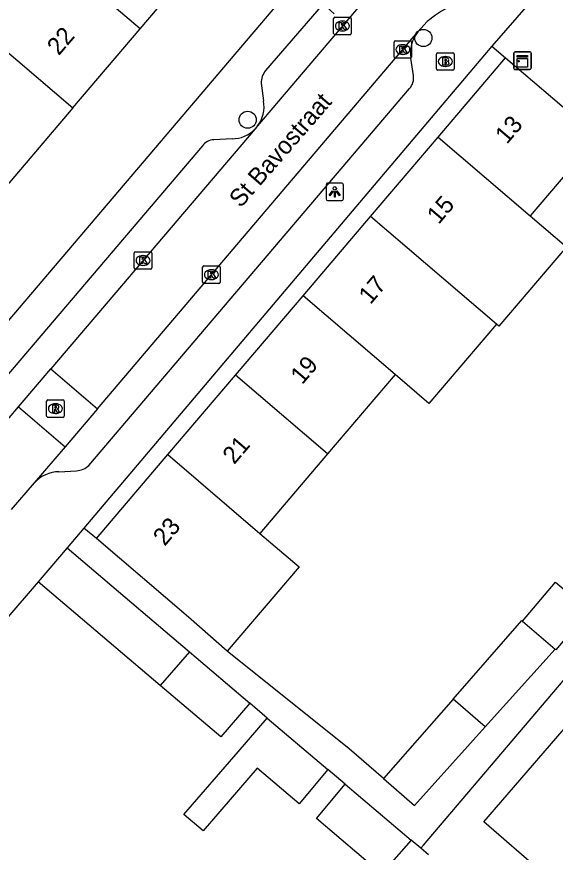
# Model space of a CAD drawing. Extents: x 162532 to 163264, y 381233 to 382042.
# Drawn here: x 163066.13 to 163096.93, y 381621.44 to 381669.17 of the extents above; entities that cross this region are included whole.
import ezdxf

# ---------------------------------------------------------------- set-up
doc = ezdxf.new("R2010")
doc.units = 0
for name, color, linetype in [('IMGEO_Boom', 7, 'Continuous'), ('IMGEO_Brandkraan', 7, 'Continuous'), ('IMGEO_Kast', 7, 'Continuous'), ('IMGEO_Kolk', 7, 'Continuous'), ('IMGEO_Lichtpunt', 7, 'Continuous'), ('IMGEO_Muur', 7, 'Continuous'), ('IMGEO_Openbare_ruimte_label', 7, 'Continuous'), ('IMGEO_Pand', 7, 'Continuous'), ('IMGEO_Pand_nummerreeks', 7, 'Continuous'), ('IMGEO_Rijbaan_lokaal_open', 7, 'Continuous'), ('IMGEO_Rioolput', 7, 'Continuous'), ('IMGEO_Voetpad_open', 7, 'Continuous')]:
    doc.layers.add(name, color=color, linetype=linetype)

msp = doc.modelspace()

# ---------------------------------------------------------------- linework, layer by layer
at = {"layer": 'IMGEO_Boom'}
for centre in [(163089.383, 381667.956), (163079.338, 381663.284)]:
    msp.add_circle(centre, 0.489, dxfattribs=at)
at = {"layer": 'IMGEO_Brandkraan'}
for p, q in [((163090.138, 381666.187), (163090.138, 381667.039)), ((163090.213, 381667.113), (163091.065, 381667.113)), ((163091.139, 381667.039), (163091.139, 381666.187)), ((163090.626, 381666.893), (163090.651, 381666.893)), ((163091.065, 381666.113), (163090.213, 381666.113)), ((163090.649, 381666.333), (163090.624, 381666.333))]:
    msp.add_line(p, q, dxfattribs=at)
for points in [[(163090.138, 381666.187), (163090.138, 381667.039)], [(163090.213, 381667.113), (163091.065, 381667.113)], [(163091.139, 381667.039), (163091.139, 381666.187)], [(163090.486, 381666.813), (163090.486, 381666.413), (163090.699, 381666.413)], [(163090.717, 381666.813), (163090.486, 381666.813)], [(163090.665, 381666.732), (163090.611, 381666.732), (163090.611, 381666.656)], [(163090.611, 381666.656), (163090.664, 381666.656)], [(163090.673, 381666.58), (163090.611, 381666.58), (163090.611, 381666.499)], [(163091.065, 381666.113), (163090.213, 381666.113)], [(163090.611, 381666.499), (163090.673, 381666.499)]]:
    msp.add_lwpolyline(points, dxfattribs=at)
for centre, radius, start, end in [((163090.215, 381667.037), 0.0765, 91.552, 178.448), ((163090.215, 381667.037), 0.0765, 91.552, 178.448), ((163091.063, 381667.037), 0.0765, 1.552, 88.448), ((163091.063, 381667.037), 0.0765, 1.552, 88.448), ((163090.666, 381666.694), 0.0379, 267.8285, 90.9355), ((163090.674, 381666.539), 0.0404, 269.8759, 90.5077), ((163090.721, 381666.668), 0.145, 59.4692, 91.5367), ((163090.746, 381666.715), 0.0922, 285.5137, 58.1501), ((163090.751, 381666.523), 0.105, 301.3115, 78.989), ((163090.215, 381666.189), 0.0765, 181.552, 268.448), ((163090.215, 381666.189), 0.0765, 181.552, 268.448), ((163090.705, 381666.664), 0.251, 268.6676, 293.5347), ((163091.063, 381666.189), 0.0765, 271.552, 358.448), ((163091.063, 381666.189), 0.0765, 271.552, 358.448)]:
    msp.add_arc(centre, radius, start, end, dxfattribs=at)
for centre, major_axis, ratio, start_param, end_param in [((163090.625, 381666.613), (-0.387, 0.002), 0.722429, 4.712389, 7.853982), ((163090.65, 381666.613), (-0.39, 0.002), 0.717154, 1.570796, 4.712389)]:
    msp.add_ellipse(centre, major_axis=major_axis, ratio=ratio, start_param=start_param, end_param=end_param, dxfattribs=at)
at = {"layer": 'IMGEO_Kast'}
for p, q in [((163094.549, 381666.235), (163094.549, 381667.076)), ((163094.549, 381667.076), (163094.549, 381666.235)), ((163094.624, 381667.16), (163095.465, 381667.16)), ((163095.465, 381667.16), (163094.624, 381667.16)), ((163095.549, 381667.085), (163095.549, 381666.244)), ((163095.549, 381666.244), (163095.549, 381667.085)), ((163095.474, 381666.16), (163094.633, 381666.16)), ((163094.633, 381666.16), (163095.474, 381666.16))]:
    msp.add_line(p, q, dxfattribs=at)
for points in [[(163094.744, 381666.95), (163095.344, 381666.95), (163095.344, 381666.865), (163094.744, 381666.865), (163094.744, 381666.95)], [(163094.744, 381666.775), (163095.344, 381666.775), (163095.344, 381666.286), (163094.744, 381666.286), (163094.744, 381666.775)]]:
    msp.add_lwpolyline(points, dxfattribs=at)
msp.add_circle((163094.828, 381666.624), 0.0377, dxfattribs=at)
for centre, start, end in [((163094.627, 381667.082), 92.4484, 184.2845), ((163094.627, 381667.082), 92.4484, 184.2845), ((163095.471, 381667.082), 2.4484, 94.2845), ((163095.471, 381667.082), 2.4484, 94.2845), ((163094.627, 381666.238), 182.4484, 274.2845), ((163094.627, 381666.238), 182.4484, 274.2845), ((163095.471, 381666.238), 272.4484, 4.2845), ((163095.471, 381666.238), 272.4484, 4.2845)]:
    msp.add_arc(centre, 0.0779, start, end, dxfattribs=at)
at = {"layer": 'IMGEO_Kolk'}
for p, q in [((163084.254, 381668.217), (163084.254, 381669.069)), ((163084.329, 381669.143), (163085.181, 381669.143)), ((163084.742, 381668.923), (163084.767, 381668.923)), ((163085.255, 381669.069), (163085.255, 381668.217)), ((163085.181, 381668.143), (163084.329, 381668.143)), ((163084.765, 381668.363), (163084.74, 381668.363)), ((163087.712, 381666.868), (163087.712, 381667.72)), ((163087.787, 381667.794), (163088.639, 381667.794)), ((163088.2, 381667.574), (163088.225, 381667.574)), ((163088.713, 381667.72), (163088.713, 381666.868)), ((163088.223, 381667.014), (163088.198, 381667.014)), ((163088.639, 381666.794), (163087.787, 381666.794)), ((163072.855, 381654.821), (163072.855, 381655.673)), ((163072.93, 381655.747), (163073.782, 381655.747)), ((163073.856, 381655.673), (163073.856, 381654.821)), ((163073.343, 381655.527), (163073.368, 381655.527)), ((163073.782, 381654.747), (163072.93, 381654.747)), ((163073.366, 381654.967), (163073.341, 381654.967)), ((163076.765, 381654.009), (163076.765, 381654.861)), ((163076.84, 381654.935), (163077.692, 381654.935)), ((163077.253, 381654.715), (163077.278, 381654.715)), ((163077.766, 381654.861), (163077.766, 381654.009)), ((163077.276, 381654.155), (163077.251, 381654.155)), ((163077.692, 381653.935), (163076.84, 381653.935))]:
    msp.add_line(p, q, dxfattribs=at)
for points in [[(163084.254, 381668.217), (163084.254, 381669.069)], [(163084.329, 381669.143), (163085.181, 381669.143)], [(163085.255, 381669.069), (163085.255, 381668.217)], [(163084.575, 381668.843), (163084.698, 381668.843), (163084.698, 381668.692), (163084.828, 381668.843), (163084.992, 381668.843), (163084.846, 381668.692), (163084.999, 381668.443), (163084.847, 381668.443), (163084.762, 381668.607), (163084.698, 381668.54), (163084.698, 381668.443), (163084.575, 381668.443), (163084.575, 381668.843)], [(163085.181, 381668.143), (163084.329, 381668.143)], [(163087.712, 381666.868), (163087.712, 381667.72)], [(163087.787, 381667.794), (163088.639, 381667.794)], [(163088.033, 381667.494), (163088.156, 381667.494), (163088.156, 381667.343), (163088.286, 381667.494), (163088.45, 381667.494), (163088.304, 381667.343), (163088.457, 381667.094), (163088.305, 381667.094), (163088.22, 381667.258), (163088.156, 381667.191), (163088.156, 381667.094), (163088.033, 381667.094), (163088.033, 381667.494)], [(163088.713, 381667.72), (163088.713, 381666.868)], [(163088.639, 381666.794), (163087.787, 381666.794)], [(163072.855, 381654.821), (163072.855, 381655.673)], [(163072.93, 381655.747), (163073.782, 381655.747)], [(163073.856, 381655.673), (163073.856, 381654.821)], [(163073.176, 381655.447), (163073.299, 381655.447), (163073.299, 381655.296), (163073.429, 381655.447), (163073.593, 381655.447), (163073.447, 381655.296), (163073.6, 381655.047), (163073.448, 381655.047), (163073.363, 381655.211), (163073.299, 381655.144), (163073.299, 381655.047), (163073.176, 381655.047), (163073.176, 381655.447)], [(163073.782, 381654.747), (163072.93, 381654.747)], [(163076.765, 381654.009), (163076.765, 381654.861)], [(163076.84, 381654.935), (163077.692, 381654.935)], [(163077.086, 381654.635), (163077.209, 381654.635), (163077.209, 381654.484), (163077.339, 381654.635), (163077.503, 381654.635), (163077.357, 381654.484), (163077.51, 381654.235), (163077.358, 381654.235), (163077.273, 381654.399), (163077.209, 381654.332), (163077.209, 381654.235), (163077.086, 381654.235), (163077.086, 381654.635)], [(163077.766, 381654.861), (163077.766, 381654.009)], [(163077.692, 381653.935), (163076.84, 381653.935)]]:
    msp.add_lwpolyline(points, dxfattribs=at)
for centre, start, end in [((163084.331, 381669.067), 91.552, 178.448), ((163084.331, 381669.067), 91.552, 178.448), ((163085.179, 381669.067), 1.552, 88.448), ((163085.179, 381669.067), 1.552, 88.448), ((163084.331, 381668.219), 181.552, 268.448), ((163084.331, 381668.219), 181.552, 268.448), ((163085.179, 381668.219), 271.552, 358.448), ((163085.179, 381668.219), 271.552, 358.448), ((163087.789, 381667.718), 91.552, 178.448), ((163087.789, 381667.718), 91.552, 178.448), ((163088.637, 381667.718), 1.552, 88.448), ((163088.637, 381667.718), 1.552, 88.448), ((163087.789, 381666.87), 181.552, 268.448), ((163087.789, 381666.87), 181.552, 268.448), ((163088.637, 381666.87), 271.552, 358.448), ((163088.637, 381666.87), 271.552, 358.448), ((163072.932, 381655.671), 91.552, 178.448), ((163072.932, 381655.671), 91.552, 178.448), ((163073.78, 381655.671), 1.552, 88.448), ((163073.78, 381655.671), 1.552, 88.448), ((163072.932, 381654.823), 181.552, 268.448), ((163072.932, 381654.823), 181.552, 268.448), ((163073.78, 381654.823), 271.552, 358.448), ((163073.78, 381654.823), 271.552, 358.448), ((163076.842, 381654.859), 91.552, 178.448), ((163076.842, 381654.859), 91.552, 178.448), ((163077.69, 381654.859), 1.552, 88.448), ((163077.69, 381654.859), 1.552, 88.448), ((163076.842, 381654.011), 181.552, 268.448), ((163076.842, 381654.011), 181.552, 268.448), ((163077.69, 381654.011), 271.552, 358.448), ((163077.69, 381654.011), 271.552, 358.448)]:
    msp.add_arc(centre, 0.0765, start, end, dxfattribs=at)
for centre, major_axis, ratio, start_param, end_param in [((163084.741, 381668.643), (-0.387, 0.002), 0.722429, 4.712389, 7.853982), ((163084.766, 381668.643), (-0.39, 0.002), 0.717154, 1.570796, 4.712389), ((163088.199, 381667.294), (-0.387, 0.002), 0.722429, 4.712389, 7.853982), ((163088.224, 381667.294), (-0.39, 0.002), 0.717154, 1.570796, 4.712389), ((163073.342, 381655.247), (-0.387, 0.002), 0.722429, 4.712389, 7.853982), ((163073.367, 381655.247), (-0.39, 0.002), 0.717154, 1.570796, 4.712389), ((163077.252, 381654.435), (-0.387, 0.002), 0.722429, 4.712389, 7.853982), ((163077.277, 381654.435), (-0.39, 0.002), 0.717154, 1.570796, 4.712389)]:
    msp.add_ellipse(centre, major_axis=major_axis, ratio=ratio, start_param=start_param, end_param=end_param, dxfattribs=at)
at = {"layer": 'IMGEO_Lichtpunt'}
for p, q in [((163083.818, 381659.567), (163083.818, 381658.76)), ((163083.818, 381659.567), (163083.818, 381658.76)), ((163084.72, 381659.662), (163083.912, 381659.662)), ((163084.72, 381659.662), (163083.912, 381659.662)), ((163084.814, 381658.76), (163084.814, 381659.567)), ((163084.814, 381658.76), (163084.814, 381659.567)), ((163083.912, 381658.666), (163084.72, 381658.666)), ((163083.912, 381658.666), (163084.72, 381658.666))]:
    msp.add_line(p, q, dxfattribs=at)
for points in [[(163084.192, 381659.231), (163084.231, 381659.203), (163084.043, 381658.941), (163084.005, 381658.968), (163084.192, 381659.231)], [(163084.294, 381659.183), (163084.341, 381659.183), (163084.341, 381658.861), (163084.294, 381658.861), (163084.294, 381659.183)], [(163084.404, 381659.203), (163084.442, 381659.23), (163084.629, 381658.968), (163084.59, 381658.94), (163084.404, 381659.203)]]:
    msp.add_lwpolyline(points, dxfattribs=at)
msp.add_circle((163084.317, 381659.365), 0.0994, dxfattribs=at)
for centre, start, end in [((163083.912, 381659.567), 90, 180), ((163083.912, 381659.567), 90, 180), ((163084.72, 381659.567), 0, 90), ((163084.72, 381659.567), 0, 90), ((163083.912, 381658.76), 180, 270), ((163083.912, 381658.76), 180, 270), ((163084.72, 381658.76), 270, 0), ((163084.72, 381658.76), 270, 360)]:
    msp.add_arc(centre, 0.0946, start, end, dxfattribs=at)
at = {"layer": 'IMGEO_Muur'}
msp.add_lwpolyline([(163067.361, 381636.896), (163065.516, 381634.738)], dxfattribs=at)
at = {"layer": 'IMGEO_Pand'}
for points in [[(163073.19, 381668.483), (163067.94, 381672.961), (163067.641, 381672.609)], [(163073.19, 381668.483), (163077.04, 381673.007)], [(163064.09, 381668.438), (163069.34, 381663.96)], [(163069.34, 381663.96), (163073.19, 381668.483)], [(163090.233, 381662.298), (163094.086, 381666.82)], [(163094.086, 381666.82), (163099.354, 381662.333)], [(163069.34, 381663.96), (163065.49, 381659.437)], [(163086.368, 381657.761), (163090.233, 381662.298)], [(163090.233, 381662.298), (163095.492, 381657.8)], [(163099.354, 381662.333), (163095.492, 381657.8)], [(163082.504, 381653.225), (163086.368, 381657.761)], [(163093.562, 381651.609), (163086.368, 381657.761)], [(163095.492, 381657.8), (163097.57, 381656.029), (163093.705, 381651.493), (163093.562, 381651.609)], [(163078.638, 381648.688), (163082.504, 381653.225)], [(163087.762, 381648.728), (163082.504, 381653.225)], [(163093.562, 381651.609), (163089.698, 381647.073), (163087.762, 381648.728)], [(163074.773, 381644.152), (163078.638, 381648.688)], [(163083.897, 381644.191), (163078.638, 381648.688)], [(163087.762, 381648.728), (163083.897, 381644.191)], [(163070.687, 381639.356), (163074.773, 381644.152)], [(163074.773, 381644.152), (163080.032, 381639.654)], [(163083.897, 381644.191), (163080.032, 381639.654)], [(163078.17, 381632.92), (163075.955, 381634.869), (163070.687, 381639.356)], [(163080.032, 381639.654), (163082.275, 381637.738), (163078.17, 381632.92)], [(163069.021, 381638.837), (163067.361, 381636.896)], [(163069.021, 381638.837), (163073.608, 381634.923), (163076.007, 381632.89)], [(163074.34, 381630.962), (163067.361, 381636.896)], [(163095.049, 381634.642), (163096.942, 381636.864), (163098.698, 381635.381), (163098.862, 381635.242)], [(163098.862, 381635.242), (163096.958, 381633.008), (163096.919, 381633.042)], [(163091.08, 381630.179), (163095.017, 381634.669), (163095.049, 381634.642)], [(163095.049, 381634.642), (163096.919, 381633.042)], [(163076.007, 381632.89), (163074.34, 381630.962)], [(163076.007, 381632.89), (163079.463, 381629.952)], [(163096.919, 381633.042), (163092.92, 381628.605)], [(163079.463, 381629.952), (163077.796, 381628.024), (163074.34, 381630.962)], [(163091.08, 381630.179), (163087.104, 381625.645)], [(163092.92, 381628.605), (163091.08, 381630.179)], [(163083.927, 381626.165), (163082.277, 381624.214), (163079.89, 381626.244), (163076.79, 381622.658), (163075.69, 381623.594), (163078.79, 381627.179), (163080.457, 381629.107)], [(163080.457, 381629.107), (163083.927, 381626.165)], [(163087.104, 381625.645), (163088.877, 381624.118), (163092.92, 381628.605)], [(163088.678, 381622.137), (163086.999, 381620.199), (163083.268, 381623.372), (163084.919, 381625.324)], [(163084.919, 381625.324), (163088.678, 381622.137)]]:
    msp.add_lwpolyline(points, dxfattribs=at)
at = {"layer": 'IMGEO_Rijbaan_lokaal_open'}
for points in [[(163094.918, 381680.596), (163079.904, 381662.933)], [(163089.068, 381668.301), (163089.601, 381668.89)], [(163070.746, 381646.776), (163089.068, 381668.301)], [(163079.764, 381662.769), (163068.08, 381649.049)], [(163079.904, 381662.933), (163079.764, 381662.769)], [(163066.232, 381646.879), (163068.08, 381649.049)], [(163068.08, 381649.049), (163070.746, 381646.776)], [(163064.334, 381644.65), (163066.232, 381646.879)], [(163066.232, 381646.879), (163068.898, 381644.606)], [(163070.746, 381646.776), (163068.898, 381644.606)], [(163068.898, 381644.606), (163067.142, 381642.543)], [(163067.142, 381642.543), (163065.82, 381641.011)]]:
    msp.add_lwpolyline(points, dxfattribs=at)
msp.add_arc((163093.516, 381664.375), 5.976, 115.348, 130.9339, dxfattribs=at)
at = {"layer": 'IMGEO_Rioolput'}
for p, q in [((163067.844, 381646.357), (163067.844, 381647.209)), ((163067.919, 381647.283), (163068.771, 381647.283)), ((163068.332, 381647.063), (163068.357, 381647.063)), ((163068.845, 381647.209), (163068.845, 381646.357)), ((163068.355, 381646.503), (163068.33, 381646.503)), ((163068.771, 381646.283), (163067.919, 381646.283))]:
    msp.add_line(p, q, dxfattribs=at)
for points in [[(163067.844, 381646.357), (163067.844, 381647.209)], [(163067.919, 381647.283), (163068.771, 381647.283)], [(163068.433, 381646.981), (163068.181, 381646.983), (163068.181, 381646.583)], [(163068.845, 381647.209), (163068.845, 381646.357)], [(163068.181, 381646.583), (163068.305, 381646.583), (163068.305, 381646.745), (163068.316, 381646.745)], [(163068.359, 381646.902), (163068.305, 381646.902), (163068.305, 381646.821)], [(163068.305, 381646.821), (163068.357, 381646.821)], [(163068.363, 381646.716), (163068.434, 381646.583), (163068.574, 381646.583), (163068.509, 381646.709)], [(163068.771, 381646.283), (163067.919, 381646.283)]]:
    msp.add_lwpolyline(points, dxfattribs=at)
for centre, radius, start, end in [((163067.921, 381647.207), 0.0765, 91.552, 178.448), ((163067.921, 381647.207), 0.0765, 91.552, 178.448), ((163068.432, 381646.871), 0.109, 350.3612, 89.416), ((163068.769, 381647.207), 0.0765, 1.552, 88.448), ((163068.769, 381647.207), 0.0765, 1.552, 88.448), ((163068.315, 381646.692), 0.0533, 26.0293, 88.6989), ((163068.341, 381647.01), 0.19, 274.7715, 282.9687), ((163068.365, 381646.806), 0.0964, 77.0061, 93.1865), ((163068.379, 381646.863), 0.0378, 276.6634, 79.6772), ((163068.43, 381646.871), 0.112, 277.5842, 350.9817), ((163068.414, 381646.656), 0.108, 29.5134, 73.7905), ((163067.921, 381646.359), 0.0765, 181.552, 268.448), ((163067.921, 381646.359), 0.0765, 181.552, 268.448), ((163068.769, 381646.359), 0.0765, 271.552, 358.448), ((163068.769, 381646.359), 0.0765, 271.552, 358.448)]:
    msp.add_arc(centre, radius, start, end, dxfattribs=at)
for centre, major_axis, ratio, start_param, end_param in [((163068.331, 381646.783), (-0.387, 0.002), 0.722429, 4.712389, 7.853982), ((163068.356, 381646.783), (-0.39, 0.002), 0.717154, 1.570796, 4.712389)]:
    msp.add_ellipse(centre, major_axis=major_axis, ratio=ratio, start_param=start_param, end_param=end_param, dxfattribs=at)
at = {"layer": 'IMGEO_Voetpad_open'}
for points in [[(163061.302, 381646.699), (163083.389, 381672.655), (163115.395, 381710.308)], [(163084.281, 381669.338), (163083.651, 381669.912), (163080.367, 381666.093)], [(163095.505, 381670.03), (163093.302, 381667.488)], [(163093.302, 381667.488), (163069.973, 381639.961)], [(163093.302, 381667.488), (163094.086, 381666.82)], [(163088.818, 381665.809), (163088.665, 381666.799)], [(163080.109, 381665.368), (163080.24, 381664.361)], [(163070.266, 381643.533), (163088.596, 381665.071)], [(163076.749, 381661.79), (163064.875, 381647.883)], [(163078.445, 381662.2), (163077.411, 381662.14)], [(163068.552, 381643.176), (163069.554, 381643.235)], [(163069.973, 381639.961), (163069.021, 381638.837)], [(163070.687, 381639.356), (163069.973, 381639.961)], [(163067.361, 381636.896), (163065.516, 381634.738), (163059.268, 381627.393)], [(163089.235, 381621.665), (163089.392, 381621.85), (163099.963, 381634.278)], [(163087.104, 381625.645), (163085.134, 381627.341), (163078.17, 381632.92)], [(163080.457, 381629.107), (163079.463, 381629.952)], [(163102.887, 381614.472), (163092.839, 381623.185), (163098.774, 381630.031), (163108.816, 381621.31), (163102.887, 381614.472)], [(163084.919, 381625.324), (163083.927, 381626.165)], [(163089.235, 381621.665), (163088.678, 381622.137)], [(163089.671, 381621.295), (163089.235, 381621.665)]]:
    msp.add_lwpolyline(points, dxfattribs=at)
for centre, radius, start, end in [((163090.554, 381667.097), 1.913, 140.9923, 188.9693), ((163081.249, 381665.371), 1.14, 140.6852, 180.1374), ((163087.919, 381665.677), 0.909, 318.1732, 8.3429), ((163078.547, 381664.006), 1.729, 321.6649, 11.854), ((163078.473, 381663.949), 1.749, 269.0879, 317.5817), ((163077.425, 381661.312), 0.828, 90.9866, 144.7443), ((163068.582, 381641.223), 1.953, 90.8734, 137.4807), ((163069.509, 381644.341), 1.107, 272.3045, 313.1179)]:
    msp.add_arc(centre, radius, start, end, dxfattribs=at)

# ---------------------------------------------------------------- texts
at = {"layer": 'IMGEO_Openbare_ruimte_label'}
msp.add_text('St Bavostraat', height=1, rotation=49.0567, dxfattribs=at).set_placement((163078.942, 381658.206))
at = {"layer": 'IMGEO_Pand_nummerreeks'}
for s, rotation, p in [('22', 49.5952, (163068.54, 381666.908)), ('13', 49.5694, (163094.157, 381661.844)), ('15', 49.5694, (163090.257, 381657.266)), ('17', 49.5694, (163086.357, 381652.689)), ('19', 49.5694, (163082.457, 381648.112)), ('21', 49.5694, (163078.571, 381643.551)), ('23', 49.5694, (163074.598, 381638.888))]:
    msp.add_text(s, height=1, rotation=rotation, dxfattribs=at).set_placement(p)

doc.saveas('drawing.dxf')
